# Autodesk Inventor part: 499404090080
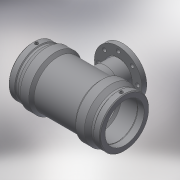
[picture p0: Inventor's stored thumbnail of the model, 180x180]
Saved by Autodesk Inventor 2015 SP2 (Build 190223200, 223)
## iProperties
Created: 2017-06
Part Number: 499404090080
Material: Generic
Description: PLASSON FLANGED TEE 90x80x90
Document SubType Name: Modeling
Designer: KIM
Mass: 57.3761 g
Surface Area: 241.06 cm^2
Volume: 57.3761 cm^3
Density: 1 g/cm^3
Appearance: Default
Author: KIM
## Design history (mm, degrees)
derived "499404.ipt"
feature "Solid1::499404.ipt"
tag "TaggingFeature1"
body "Solid1"
other parameters: "d13" = 294, "d14" = 17.6296, "d17" = 81, "d19" = 3.52592, "d20" = 168 deg, "d22" = 105.09, "d23" = 113, "d24" = 101.9373, "d25" = 135 deg, "d26" = 199.92, "d27" = 135 deg, "d29" = 71, "d35" = 15, "d39" = 5 deg, "d45" = 4, "d46" = 14, "d47" = 0, "d48" = -165, "d55" = 101.7, "d56" = 113, "d57" = 99.96, "d58" = 135 deg, "d59" = 71, "d60" = 71, "d61" = 135 deg, "d62" = 165, "d72" = 129.948, "d73" = 64.974, "d74" = -165, "d84" = 165, "d87" = 138, "d89" = 96, "d91" = 15 deg, "d92" = 104, "d95" = 4.14, "d97" = 18, "d100" = 0, "d102" = 360 deg, "d105" = 0, "d107" = 0, "d108" = 3, "d109" = 0, "d110" = 21.3, "d111" = 7.1, "L_" = 294, "L_1" = 71, "D_" = 113, "A_" = 71, "d_2" = 12, "H_" = 165, "d_1" = 138, "s_" = 18
